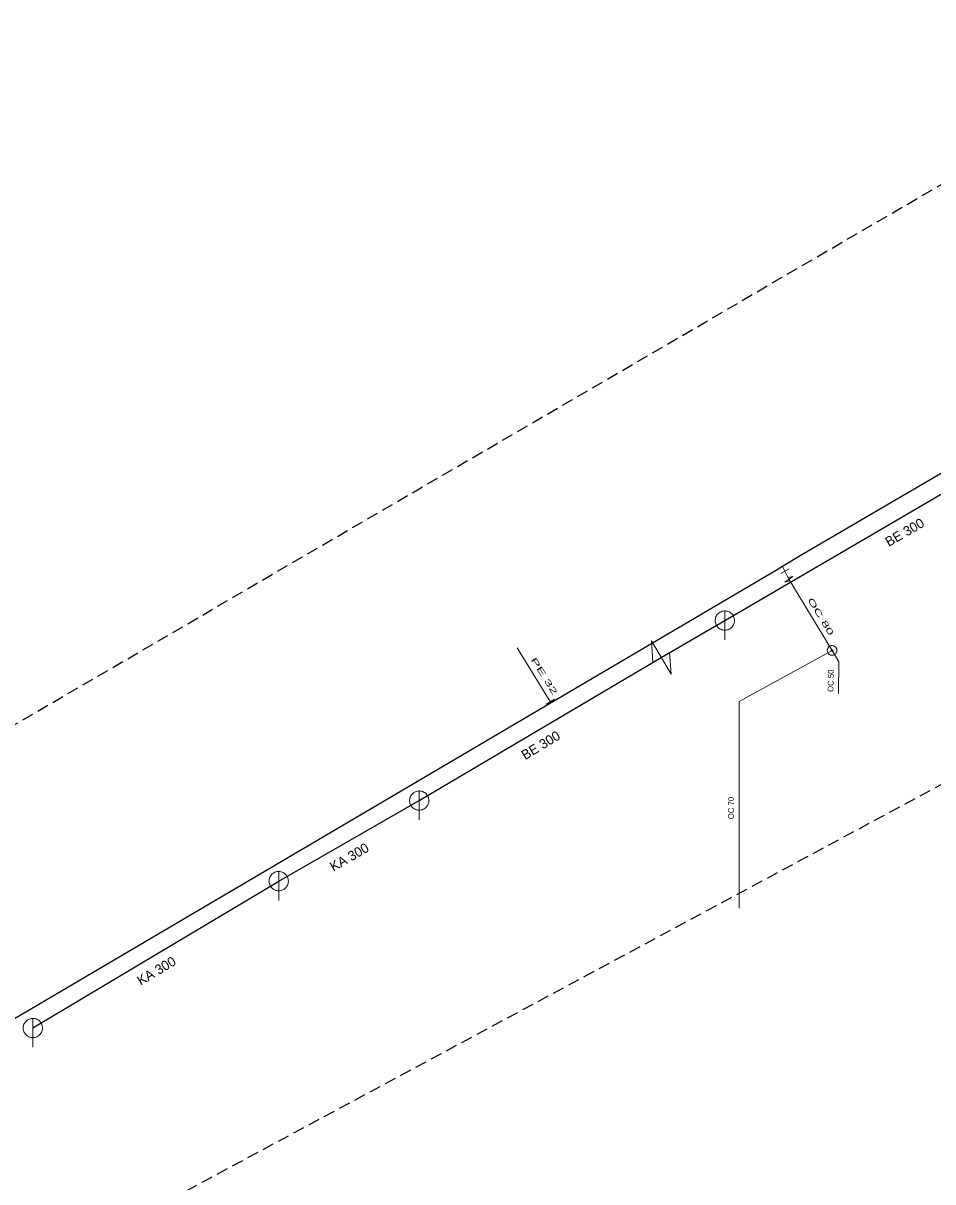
# Model space of a CAD drawing. Extents: x -689189 to -688666, y -973229 to -972850.
# Drawn here: x -688952.7 to -688858.3, y -973042.2 to -972922 of the extents above; entities that cross this region are included whole.
import ezdxf

# ---------------------------------------------------------------- set-up
doc = ezdxf.new("R2010")
doc.units = 0
doc.header["$LTSCALE"] = 0.4
doc.linetypes.add('MEDIUM_DASHED', pattern=[4.5, 3, -1.5])
doc.layers.add('1', color=7, linetype='Continuous')
for name, color, linetype, lineweight in [('13', 7, 'Continuous', 13), ('14', 7, 'Continuous', 13), ('17', 7, 'Continuous', 25), ('22', 7, 'Continuous', 13), ('31', 7, 'Continuous', 13), ('34', 7, 'Continuous', 13), ('47', 7, 'Continuous', 13), ('63', 7, 'MEDIUM_DASHED', 25)]:
    doc.layers.add(name, color=color, linetype=linetype, lineweight=lineweight)

msp = doc.modelspace()

# ---------------------------------------------------------------- linework, layer by layer
at = {"layer": '13'}
for points in [[(-688873.897, -972978.38), (-688873.64, -972978.84), (-688873.25, -972979.69), (-688868.748, -972987.078)], [(-688897.989, -972992.379), (-688898.629, -972991.39), (-688901.414, -972986.817)], [(-688868.748, -972987.078), (-688878.394, -972992.374), (-688878.394, -973013.805)], [(-688868.748, -972987.078), (-688868.036, -972988.246), (-688868.076, -972991.54)]]:
    msp.add_lwpolyline(points, dxfattribs=at)
at = {"layer": '14'}
msp.add_line((-688897.906, -972992.515), (-688897.989, -972992.379), dxfattribs=at)
at = {"layer": '14', "lineweight": 25}
msp.add_lwpolyline([(-688951.66, -973026.25), (-688926.154, -973011.013), (-688911.58, -973002.657), (-688886.468, -972987.81), (-688879.879, -972983.977), (-688842.688, -972962.265)], dxfattribs=at)
at = {"layer": '17'}
msp.add_lwpolyline([(-688793.177, -972931.292), (-688807.995, -972940.316), (-688831.953, -972953.798), (-688872.059, -972977.27), (-688873.897, -972978.38), (-688874.46, -972978.719), (-688897.906, -972992.515), (-688964.11, -973031.504), (-688973.449, -973037.003), (-688975.824, -973038.94)], dxfattribs=at)
at = {"layer": '22'}
for p, q in [((-688879.879, -972985.977), (-688879.878, -972982.977)), ((-688911.58, -973004.657), (-688911.579, -973001.657)), ((-688926.154, -973013.013), (-688926.153, -973010.013)), ((-688951.66, -973028.25), (-688951.659, -973025.25))]:
    msp.add_line(p, q, dxfattribs=at)
for points in [[(-688878.879, -972983.977), (-688878.884, -972983.868), (-688878.902, -972983.76), (-688878.932, -972983.654), (-688878.972, -972983.553), (-688879.024, -972983.456), (-688879.086, -972983.366), (-688879.158, -972983.283), (-688879.238, -972983.209), (-688879.326, -972983.143), (-688879.42, -972983.088), (-688879.52, -972983.043), (-688879.625, -972983.01), (-688879.732, -972982.988), (-688879.841, -972982.978), (-688879.951, -972982.98), (-688880.059, -972982.994), (-688880.166, -972983.019), (-688880.269, -972983.056), (-688880.367, -972983.105), (-688880.459, -972983.163), (-688880.545, -972983.232), (-688880.622, -972983.309), (-688880.691, -972983.395), (-688880.75, -972983.487), (-688880.798, -972983.585), (-688880.835, -972983.688), (-688880.861, -972983.795), (-688880.875, -972983.903), (-688880.878, -972984.013), (-688880.868, -972984.122), (-688880.847, -972984.229), (-688880.813, -972984.333), (-688880.769, -972984.433), (-688880.714, -972984.528), (-688880.648, -972984.616), (-688880.574, -972984.696), (-688880.491, -972984.768), (-688880.401, -972984.83), (-688880.305, -972984.882), (-688880.203, -972984.923), (-688880.098, -972984.953), (-688879.99, -972984.971), (-688879.88, -972984.977), (-688879.771, -972984.971), (-688879.663, -972984.953), (-688879.558, -972984.924), (-688879.456, -972984.883), (-688879.359, -972984.831), (-688879.269, -972984.769), (-688879.186, -972984.698), (-688879.111, -972984.618), (-688879.046, -972984.53), (-688878.99, -972984.436), (-688878.946, -972984.336), (-688878.912, -972984.232), (-688878.89, -972984.124), (-688878.88, -972984.015)], [(-688910.58, -973002.657), (-688910.585, -973002.548), (-688910.603, -973002.44), (-688910.633, -973002.334), (-688910.673, -973002.233), (-688910.725, -973002.136), (-688910.787, -973002.046), (-688910.859, -973001.963), (-688910.939, -973001.889), (-688911.027, -973001.823), (-688911.121, -973001.768), (-688911.221, -973001.723), (-688911.326, -973001.69), (-688911.433, -973001.668), (-688911.542, -973001.658), (-688911.652, -973001.66), (-688911.76, -973001.674), (-688911.867, -973001.699), (-688911.97, -973001.736), (-688912.068, -973001.785), (-688912.16, -973001.843), (-688912.246, -973001.912), (-688912.323, -973001.989), (-688912.392, -973002.075), (-688912.451, -973002.167), (-688912.499, -973002.265), (-688912.536, -973002.368), (-688912.562, -973002.475), (-688912.576, -973002.583), (-688912.579, -973002.693), (-688912.569, -973002.802), (-688912.548, -973002.909), (-688912.514, -973003.013), (-688912.47, -973003.113), (-688912.415, -973003.208), (-688912.349, -973003.296), (-688912.275, -973003.376), (-688912.192, -973003.448), (-688912.102, -973003.51), (-688912.006, -973003.562), (-688911.904, -973003.603), (-688911.799, -973003.633), (-688911.691, -973003.651), (-688911.581, -973003.657), (-688911.472, -973003.651), (-688911.364, -973003.633), (-688911.259, -973003.604), (-688911.157, -973003.563), (-688911.06, -973003.511), (-688910.97, -973003.449), (-688910.887, -973003.378), (-688910.812, -973003.298), (-688910.747, -973003.21), (-688910.691, -973003.116), (-688910.647, -973003.016), (-688910.613, -973002.912), (-688910.591, -973002.804), (-688910.581, -973002.695)], [(-688925.154, -973011.013), (-688925.159, -973010.904), (-688925.177, -973010.796), (-688925.207, -973010.69), (-688925.247, -973010.589), (-688925.299, -973010.492), (-688925.361, -973010.402), (-688925.433, -973010.319), (-688925.513, -973010.245), (-688925.601, -973010.179), (-688925.695, -973010.124), (-688925.795, -973010.079), (-688925.9, -973010.046), (-688926.007, -973010.024), (-688926.116, -973010.014), (-688926.226, -973010.016), (-688926.334, -973010.03), (-688926.441, -973010.055), (-688926.544, -973010.092), (-688926.642, -973010.141), (-688926.734, -973010.199), (-688926.82, -973010.268), (-688926.897, -973010.345), (-688926.966, -973010.431), (-688927.025, -973010.523), (-688927.073, -973010.621), (-688927.11, -973010.724), (-688927.136, -973010.831), (-688927.15, -973010.939), (-688927.153, -973011.049), (-688927.143, -973011.158), (-688927.122, -973011.265), (-688927.088, -973011.369), (-688927.044, -973011.469), (-688926.989, -973011.564), (-688926.923, -973011.652), (-688926.849, -973011.732), (-688926.766, -973011.804), (-688926.676, -973011.866), (-688926.58, -973011.918), (-688926.478, -973011.959), (-688926.373, -973011.989), (-688926.265, -973012.007), (-688926.155, -973012.013), (-688926.046, -973012.007), (-688925.938, -973011.989), (-688925.833, -973011.96), (-688925.731, -973011.919), (-688925.634, -973011.867), (-688925.544, -973011.805), (-688925.461, -973011.734), (-688925.386, -973011.654), (-688925.321, -973011.566), (-688925.265, -973011.472), (-688925.221, -973011.372), (-688925.187, -973011.268), (-688925.165, -973011.16), (-688925.155, -973011.051)], [(-688950.66, -973026.25), (-688950.665, -973026.141), (-688950.683, -973026.033), (-688950.713, -973025.927), (-688950.753, -973025.826), (-688950.805, -973025.729), (-688950.867, -973025.639), (-688950.939, -973025.556), (-688951.019, -973025.482), (-688951.107, -973025.416), (-688951.201, -973025.361), (-688951.301, -973025.316), (-688951.406, -973025.283), (-688951.513, -973025.261), (-688951.622, -973025.251), (-688951.732, -973025.253), (-688951.84, -973025.267), (-688951.947, -973025.292), (-688952.05, -973025.329), (-688952.148, -973025.378), (-688952.24, -973025.436), (-688952.326, -973025.505), (-688952.403, -973025.582), (-688952.472, -973025.668), (-688952.531, -973025.76), (-688952.579, -973025.858), (-688952.616, -973025.961), (-688952.642, -973026.068), (-688952.656, -973026.176), (-688952.659, -973026.286), (-688952.649, -973026.395), (-688952.628, -973026.502), (-688952.594, -973026.606), (-688952.55, -973026.706), (-688952.495, -973026.801), (-688952.429, -973026.889), (-688952.355, -973026.969), (-688952.272, -973027.041), (-688952.182, -973027.103), (-688952.086, -973027.155), (-688951.984, -973027.196), (-688951.879, -973027.226), (-688951.771, -973027.244), (-688951.661, -973027.25), (-688951.552, -973027.244), (-688951.444, -973027.226), (-688951.339, -973027.197), (-688951.237, -973027.156), (-688951.14, -973027.104), (-688951.05, -973027.042), (-688950.967, -973026.971), (-688950.892, -973026.891), (-688950.827, -973026.803), (-688950.771, -973026.709), (-688950.727, -973026.609), (-688950.693, -973026.505), (-688950.671, -973026.397), (-688950.661, -973026.288)]]:
    msp.add_lwpolyline(points, close=True, dxfattribs=at)
at = {"layer": '31'}
msp.add_lwpolyline([(-688887.331, -972988.314), (-688887.476, -972986.083), (-688885.459, -972989.537), (-688885.604, -972987.306)], dxfattribs=at)
at = {"layer": '34'}
for p, q in [((-688873.204, -972978.595), (-688874.076, -972979.083)), ((-688898.414, -972992.641), (-688897.562, -972992.117))]:
    msp.add_line(p, q, dxfattribs=at)
at = {"layer": '47'}
msp.add_line((-688872.836, -972979.392), (-688873.333, -972979.507), dxfattribs=at)
msp.add_lwpolyline([(-688872.836, -972979.392), (-688873.663, -972979.987), (-688873.166, -972979.872)], dxfattribs=at)
for points in [[(-688868.248, -972987.078), (-688868.251, -972987.026), (-688868.259, -972986.973), (-688868.273, -972986.924), (-688868.291, -972986.875), (-688868.315, -972986.828), (-688868.344, -972986.784), (-688868.377, -972986.744), (-688868.414, -972986.706), (-688868.454, -972986.674), (-688868.498, -972986.645), (-688868.545, -972986.62), (-688868.594, -972986.603), (-688868.644, -972986.589), (-688868.696, -972986.581), (-688868.748, -972986.578), (-688868.8, -972986.581), (-688868.852, -972986.589), (-688868.903, -972986.603), (-688868.951, -972986.62), (-688868.998, -972986.645), (-688869.042, -972986.674), (-688869.083, -972986.706), (-688869.12, -972986.744), (-688869.153, -972986.784), (-688869.181, -972986.828), (-688869.205, -972986.875), (-688869.224, -972986.924), (-688869.237, -972986.973), (-688869.245, -972987.026), (-688869.248, -972987.078), (-688869.245, -972987.13), (-688869.237, -972987.182), (-688869.224, -972987.233), (-688869.205, -972987.281), (-688869.181, -972987.328), (-688869.153, -972987.372), (-688869.12, -972987.413), (-688869.083, -972987.45), (-688869.042, -972987.483), (-688868.998, -972987.511), (-688868.951, -972987.535), (-688868.903, -972987.554), (-688868.852, -972987.566), (-688868.8, -972987.575), (-688868.748, -972987.578), (-688868.696, -972987.575), (-688868.644, -972987.566), (-688868.594, -972987.554), (-688868.545, -972987.535), (-688868.498, -972987.511), (-688868.454, -972987.483), (-688868.414, -972987.45), (-688868.377, -972987.413), (-688868.344, -972987.372), (-688868.315, -972987.328), (-688868.291, -972987.281), (-688868.273, -972987.233), (-688868.259, -972987.182), (-688868.251, -972987.13)], [(-688868.666, -972987.078), (-688868.666, -972987.069), (-688868.668, -972987.061), (-688868.67, -972987.053), (-688868.673, -972987.044), (-688868.677, -972987.037), (-688868.682, -972987.03), (-688868.687, -972987.022), (-688868.693, -972987.017), (-688868.7, -972987.012), (-688868.707, -972987.007), (-688868.715, -972987.003), (-688868.723, -972987), (-688868.731, -972986.998), (-688868.739, -972986.995), (-688868.748, -972986.995), (-688868.757, -972986.995), (-688868.765, -972986.998), (-688868.773, -972987), (-688868.781, -972987.003), (-688868.789, -972987.007), (-688868.796, -972987.012), (-688868.803, -972987.017), (-688868.809, -972987.022), (-688868.815, -972987.03), (-688868.819, -972987.037), (-688868.823, -972987.044), (-688868.826, -972987.053), (-688868.828, -972987.061), (-688868.83, -972987.069), (-688868.83, -972987.078), (-688868.83, -972987.087), (-688868.828, -972987.095), (-688868.826, -972987.103), (-688868.823, -972987.111), (-688868.819, -972987.119), (-688868.815, -972987.125), (-688868.809, -972987.133), (-688868.803, -972987.139), (-688868.796, -972987.145), (-688868.789, -972987.149), (-688868.781, -972987.152), (-688868.773, -972987.156), (-688868.765, -972987.157), (-688868.757, -972987.16), (-688868.748, -972987.16), (-688868.739, -972987.16), (-688868.731, -972987.157), (-688868.723, -972987.156), (-688868.715, -972987.152), (-688868.707, -972987.149), (-688868.7, -972987.145), (-688868.693, -972987.139), (-688868.687, -972987.133), (-688868.682, -972987.125), (-688868.677, -972987.119), (-688868.673, -972987.111), (-688868.67, -972987.103), (-688868.668, -972987.095), (-688868.666, -972987.087)]]:
    msp.add_lwpolyline(points, close=True, dxfattribs=at)
at = {"layer": '63'}
msp.add_lwpolyline([(-689164.065, -973177.51), (-689187.511, -973131.176), (-688767.155, -972886.107), (-688767.155, -972886.107), (-688777.761, -972958.121), (-688777.761, -972958.121), (-688989.335, -973072.002), (-688989.335, -973072.002)], close=True, dxfattribs=at)

# ---------------------------------------------------------------- texts
at = {"layer": '1'}
for s, height, rotation, p in [('BE 300', 1, 30, (-688862.873, -972976.348)), ('OC 50 ', 0.6, 89, (-688868.615, -972991.386)), ('BE 300', 1, 31, (-688900.595, -972998.469)), ('OC 70 ', 0.6, 90, (-688878.935, -973004.588)), ('KA 300', 1, 30, (-688920.481, -973010.048)), ('KA 300', 1, 31, (-688940.464, -973021.873))]:
    msp.add_text(s, height=height, rotation=rotation, dxfattribs=at).set_placement(p)
for s, rotation, width, p in [('OC 80 ', 301, 1.9, (-688871.316, -972981.821)), ('PE 32 ', 302, 2, (-688900.026, -972988.036))]:
    msp.add_text(s, height=0.6, rotation=rotation, dxfattribs=dict(at, width=width)).set_placement(p)

doc.saveas('drawing.dxf')
